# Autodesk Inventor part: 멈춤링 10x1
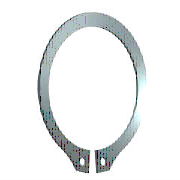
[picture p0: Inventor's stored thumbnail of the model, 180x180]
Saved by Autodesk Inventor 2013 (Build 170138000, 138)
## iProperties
IsCustomPart: 0
Created: 2015-11
Part Number: 멈춤링 10x1
Material: 스테인리스강
Description: 리테이닝 링(C형)
Document SubType Name: Modeling
Standard: KS B 1336
Designer: mdu
Standards Organization: KS
Language: ko-KR
Size Designation: 10 x 1
Categories: <MemberInstance><Categories><Category DisplayName="샤프트 부품" InternalName="7f7aeb1f-a693-4053-b835-cee3144e0d98" Mnemonic="SHFT"><Category DisplayName="써클립" Inter
Density: 8.08 g/cm^3
Mass: 0.434926 g
Surface Area: 1.9243 cm^2
Volume: 0.0538275 cm^3
Author: mdu
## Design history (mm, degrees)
sketch "스케치1"
  geometry: L1 (-6, 0)-(6, 0) reference; L2 (0, 20.189)-(0, -80.536) reference; L3 (-48.09, 0)-(48.09, 0) reference; L4 (-0.3, -9.791)-(-0.3, -12.791); L5 (-0.3, -6.54)-(-0.3, -13.29); L6 (-2.795, 1.6)-(3.672, 1.6); L7 (0.3, -6.54)-(0.3, -13.29); L8 (0.3, -9.791)-(0.3, -12.791); C1 r 0.6 at (-1.2, -11.486); C2 r 0.6 at (1.2, -11.486); A1 r 4.8 centre (0, -5) between (0.3, -9.791) and (-0.3, -9.791); A2 r 6.2 centre (0, -4.6) between (2.988, -10.033) and (-2.988, -10.033); A3 r 7.796 centre (0, -5) between (-1.418, -12.666) and (-0.3, -12.791); A4 r 1.2 centre (-1.2, -11.486) between (-2.383, -11.285) and (-1.418, -12.666); A5 r 1.2 centre (-3.566, -11.084) between (-2.383, -11.285) and (-2.988, -10.033); A6 r 1.2 centre (3.566, -11.084) between (2.988, -10.033) and (2.383, -11.285); A7 r 1.2 centre (1.2, -11.486) between (1.418, -12.666) and (2.383, -11.285); A8 r 7.796 centre (0, -5) between (0.3, -12.791) and (1.418, -12.666)
  constraints: 16 point on circle, 12 end point, 10 centre point, 9 symmetric about line, 5 point on line, 4 tangent, 3 coincident, 2 horizontal, 1 perpendicular, 1 vertical, 5 other
  dimensions: "d0" = 9.6 diameter of A1 (= ND); "d1" = 3 distance of L4.end L4.start (= SRB2); "d6" = 0.3 distance between parallel lines of L2 L5 (= 0.25 x SD5); "d7" = 1.6 distance between parallel lines of L6 L3 (= SRB1); "d8" = 0.4 distance of A1.centre A2.centre (= 0.25 x SRB1); "d9" = 1.2 radius of A4 (= SD5); "d10" = 1.2 radius of A5 (= SD5); "d11" = 0.9 distance from line of L4 A4.centre (= 0.75 x SD5); "d12" = 1.2 diameter of C1 (= SD5); "d13" = 1.2 diameter of C2 (= SD5); "d14" = 5 distance from line of A1.centre L1 (= 0.5 x WD)
extrude "본체" new body sketch "스케치1" distance "d2" = 1 (= SD); taper "d3" = 0 deg
workaxis "Work Axis1"
workplane "Work Plane1"
body "Solid1"
other parameters: "SD" = 1 [user parameter; used in 1 equation term], "SRB1" = 1.6 [user parameter; used in 2 equation terms], "ND" = 9.6 [user parameter; used in 1 equation term], "SRB2" = 3 [user parameter; used in 1 equation term], "SD5" = 1.2 [user parameter; used in 6 equation terms], "d15" = 0, "d16" = 0, "d17" = 0, "d41" = 0, "d42" = 0, "SD3" = 9.3 [user parameter], "WDMAX" = 11 [user parameter]
